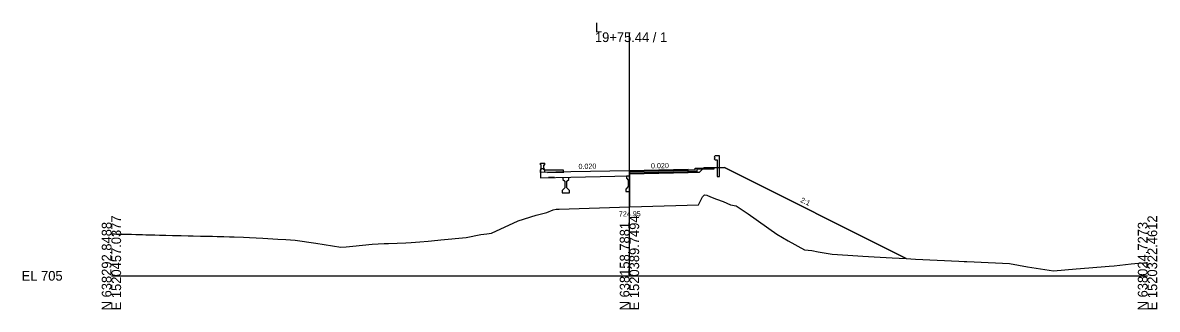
# Model space of a CAD drawing. Extents: x -26 to 3903, y -10 to 9531.
# Drawn here: x 2274.3 to 2602.8, y -9.7 to 73.3 of the extents above; entities that cross this region are included whole.
import ezdxf

# ---------------------------------------------------------------- set-up
doc = ezdxf.new("R2010")
doc.units = 0
for name, color, linetype in [('Exist Cross Section Cell', 7, 'Continuous'), ('Exist XS Center Line Elevation Label', 7, 'Continuous'), ('Exist XS Ground Line', 7, 'Continuous'), ('Old_Level_63', 7, 'Continuous'), ('Prop CMT Guardrail Graphics', 7, 'Continuous'), ('Prop CMT Pvmt Course 1', 7, 'Continuous'), ('Prop CMT Pvmt Course 3', 7, 'Continuous'), ('Prop CMT Pvmt Surface', 7, 'Continuous'), ('Prop CMT Slope Grass', 7, 'Continuous'), ('Prop CMT Subgrade Earthwork', 7, 'Continuous'), ('Prop XS Conc Monolithic Island', 7, 'Continuous'), ('Prop XS Earthwork Shape', 7, 'Continuous'), ('Prop XS Finish Grade', 7, 'Continuous'), ('Prop XS Finish Grade Concrete', 7, 'Continuous'), ('Prop XS SE Text', 7, 'Continuous'), ('Prop XS Side Slope Text', 7, 'Continuous')]:
    doc.layers.add(name, color=color, linetype=linetype)

msp = doc.modelspace()

# ---------------------------------------------------------------- linework, layer by layer
at = {"layer": 'Exist Cross Section Cell'}
for p, q in [((2450, 0), (2450, 70.48)), ((2300, 0), (2450, 0)), ((2450, 0), (2600, 0))]:
    msp.add_line(p, q, dxfattribs=at)
at = {"layer": 'Exist XS Ground Line'}
msp.add_lwpolyline([(2300, 12.12), (2300.89, 12.11), (2301.45, 12.1), (2303.1, 12.08), (2305.08, 12.06), (2305.8, 12.03), (2307.02, 11.98), (2308.33, 11.95), (2309.01, 11.93), (2309.93, 11.91), (2312.01, 11.85), (2312.55, 11.84), (2313.92, 11.8), (2314.59, 11.79), (2315.77, 11.76), (2317.64, 11.71), (2318.14, 11.7), (2320.19, 11.65), (2322.25, 11.6), (2323.23, 11.58), (2323.71, 11.57), (2325.79, 11.52), (2326.94, 11.49), (2328.82, 11.45), (2329.27, 11.44), (2330.64, 11.4), (2331.4, 11.39), (2332.52, 11.36), (2334.16, 11.32), (2334.85, 11.3), (2335.54, 11.28), (2338.23, 11.2), (2340.02, 11.1), (2343.85, 10.89), (2348.14, 10.63), (2350.47, 10.49), (2353.17, 10.33), (2359.2, 9.41), (2366.38, 8.29), (2368, 8.41), (2369.94, 8.6), (2375.5, 9.18), (2379.01, 9.31), (2379.62, 9.34), (2380.26, 9.4), (2385.25, 9.53), (2386.75, 9.67), (2389.28, 9.85), (2391.7, 10.01), (2394.48, 10.32), (2395.39, 10.42), (2402.69, 11.13), (2406.92, 11.94), (2408.71, 12.12), (2410.04, 12.37), (2417.77, 15.9), (2422.95, 17.52), (2426.12, 18.33), (2427.92, 19.15), (2428.76, 19.28), (2429.65, 19.31), (2450, 19.94), (2453.47, 20.05), (2469.97, 20.6), (2471.15, 22.85), (2471.71, 23.49), (2472.44, 23.37), (2473.44, 22.88), (2475.18, 22.15), (2477.17, 21.54), (2479.25, 20.57), (2480.86, 20.25), (2484.37, 17.97), (2492.63, 12.04), (2496, 10.14), (2500.71, 7.49), (2502.76, 7.3), (2504.6, 6.95), (2508.72, 6.27), (2513.21, 5.94), (2517.56, 5.67), (2520.9, 5.45), (2526.02, 5.17), (2530.1, 5.05), (2532.8, 4.87), (2545.33, 4.26), (2546.9, 4.17), (2547.68, 4.12), (2549.77, 4.04), (2560.06, 3.56), (2565.27, 2.59), (2572.75, 1.44), (2579.34, 2.07), (2583.04, 2.34), (2588.92, 2.8), (2590.36, 2.91), (2595.3, 3.47), (2597.4, 3.7), (2598.98, 3.77), (2600, 3.8)], dxfattribs=at)
at = {"layer": 'Old_Level_63'}
for p, q in [((2467, 30.16), (2467, 30.74)), ((2469.5, 30.21), (2467, 30.16)), ((2469.5, 31.2), (2469.5, 30.21))]:
    msp.add_line(p, q, dxfattribs=at)
for points in [[(2426.29, 29.93), (2431, 30.02)], [(2467, 30.16), (2467, 30.74)], [(2469.5, 30.89), (2474.5, 30.98)], [(2474.5, 30.98), (2474.5, 31.3)], [(2428.25, 28.47), (2427.42, 28.45), (2426.58, 28.43)]]:
    msp.add_lwpolyline(points, dxfattribs=at)
at = {"layer": 'Prop CMT Guardrail Graphics'}
for points in [[(2476.11, 34.76), (2474.77, 34.76), (2474.5, 34.46)], [(2474.5, 34.46), (2474.77, 34.17)], [(2474.77, 34.17), (2474.5, 33.88)], [(2474.5, 33.88), (2474.77, 33.59), (2475.44, 33.59)], [(2475.44, 33.59), (2475.44, 28.76)], [(2476.11, 28.76), (2476.11, 34.76)], [(2475.44, 28.76), (2476.11, 28.76)]]:
    msp.add_lwpolyline(points, dxfattribs=at)
at = {"layer": 'Prop CMT Pvmt Course 1'}
msp.add_lwpolyline([(2467, 30.49), (2450, 30.15)], dxfattribs=at)
at = {"layer": 'Prop CMT Pvmt Course 3'}
msp.add_lwpolyline([(2450, 29.82), (2467, 30.16)], dxfattribs=at)
at = {"layer": 'Prop CMT Pvmt Surface'}
msp.add_line((2467, 30.74), (2450, 30.4), dxfattribs=at)
at = {"layer": 'Prop CMT Slope Grass'}
for p, q in [((2450, 30.4), (2450, 19.94)), ((2474.5, 31.3), (2477.5, 31.36)), ((2477.5, 31.36), (2530.13, 5.05))]:
    msp.add_line(p, q, dxfattribs=at)
at = {"layer": 'Prop CMT Subgrade Earthwork'}
for points in [[(2450, 29.57), (2467, 29.91)], [(2467, 29.91), (2470.25, 29.97), (2471.51, 31.24)]]:
    msp.add_lwpolyline(points, dxfattribs=at)
at = {"layer": 'Prop XS Conc Monolithic Island'}
for p, q in [((2424.22, 32.14), (2424.22, 32.64)), ((2424.22, 32.64), (2425.47, 32.64)), ((2424.47, 32.14), (2424.22, 32.14)), ((2424.22, 29.89), (2424.22, 30.64)), ((2424.22, 30.64), (2424.47, 30.64)), ((2424.47, 30.64), (2424.47, 32.14)), ((2425.22, 30.64), (2425.22, 32.14)), ((2425.22, 32.14), (2425.47, 32.14)), ((2425.47, 30.64), (2425.22, 30.64)), ((2425.47, 32.14), (2425.47, 32.64)), ((2425.47, 29.89), (2425.47, 30.64))]:
    msp.add_line(p, q, dxfattribs=at)
for points in [[(2450, 30.4), (2433, 30.06), (2424.22, 29.89)], [(2424.22, 29.89), (2424.25, 28.39)], [(2424.25, 28.39), (2433, 28.56), (2450, 28.9)], [(2430.74, 28.52), (2430.74, 27.87)], [(2430.74, 27.87), (2431.24, 27.37)], [(2431.24, 27.37), (2431.24, 25.45)], [(2431.91, 27.37), (2432.41, 27.87)], [(2431.91, 25.45), (2431.91, 27.37)], [(2432.41, 27.87), (2432.41, 28.55)], [(2450, 28.9), (2449.17, 28.88)], [(2449.17, 28.88), (2449.17, 28.23)], [(2449.17, 28.23), (2449.67, 27.73)], [(2449.67, 27.73), (2449.67, 25.82)], [(2431.24, 25.45), (2430.49, 24.7)], [(2430.49, 24.7), (2430.49, 24.03)], [(2430.49, 24.03), (2431.58, 24.03), (2432.66, 24.03)], [(2432.66, 24.7), (2431.91, 25.45)], [(2432.66, 24.03), (2432.66, 24.7)], [(2449.67, 25.82), (2448.92, 25.07)], [(2448.92, 25.07), (2448.92, 24.4)], [(2448.92, 24.4), (2450, 24.4)]]:
    msp.add_lwpolyline(points, dxfattribs=at)
at = {"layer": 'Prop XS Earthwork Shape'}
for points in [[(2520.9, 5.45), (2526.02, 5.17), (2530.13, 5.05), (2477.5, 31.36), (2474.5, 31.3), (2471.51, 31.24), (2470.25, 29.97), (2467, 29.91), (2450, 29.57), (2450, 19.94), (2453.47, 20.05), (2469.97, 20.6), (2471.15, 22.85), (2471.71, 23.49), (2472.44, 23.37), (2473.44, 22.88), (2475.18, 22.15), (2477.17, 21.54), (2479.25, 20.57), (2480.86, 20.25), (2484.37, 17.97), (2492.63, 12.04), (2496, 10.14), (2500.71, 7.49), (2502.76, 7.3), (2504.6, 6.95), (2508.72, 6.27), (2513.21, 5.94), (2517.56, 5.67)], [(2472.44, 23.37), (2473.44, 22.88), (2475.18, 22.15), (2477.17, 21.54), (2479.25, 20.57), (2480.86, 20.25), (2484.37, 17.97), (2492.63, 12.04), (2496, 10.14), (2500.71, 7.49), (2502.76, 7.3), (2504.6, 6.95), (2508.72, 6.27), (2513.21, 5.94), (2517.56, 5.67), (2520.9, 5.45), (2526.02, 5.17), (2530.13, 5.05), (2477.5, 31.36), (2474.5, 31.3), (2471.51, 31.24), (2470.25, 29.97), (2467, 29.91), (2450, 29.57), (2450, 19.94), (2453.47, 20.05), (2469.97, 20.6), (2471.15, 22.85), (2471.71, 23.49)]]:
    msp.add_lwpolyline(points, close=True, dxfattribs=at)
at = {"layer": 'Prop XS Finish Grade'}
msp.add_line((2430.93, 30.02), (2430.93, 30.58), dxfattribs=at)
msp.add_lwpolyline([(2430.93, 30.02), (2430.93, 30.58), (2425.43, 30.63), (2425.43, 30.97), (2424.22, 30.97), (2424.22, 29.89)], dxfattribs=at)
at = {"layer": 'Prop XS Finish Grade Concrete'}
for points in [[(2467, 30.74), (2469, 30.7), (2469, 31.2), (2469.5, 31.2)], [(2469.5, 31.2), (2474.5, 31.3)]]:
    msp.add_lwpolyline(points, dxfattribs=at)

# ---------------------------------------------------------------- texts
at = {"layer": 'Exist Cross Section Cell'}
for s, p in [('L', (2440, 70.48)), ('19+75.44 / 1', (2440, 67.68)), ('EL 705', (2274, -1.4))]:
    msp.add_text(s, height=2.8, dxfattribs=at).set_placement(p)
for s, p in [('E 1520457.0377', (2302.8, -10)), ('E 1520389.7494', (2452.8, -10)), ('E 1520322.4612', (2602.8, -10)), ('N 638292.8488', (2300, -10)), ('N 638158.7881', (2450, -10)), ('N 638024.7273', (2600, -10))]:
    msp.add_text(s, height=2.8, rotation=90, dxfattribs=at).set_placement(p)
at = {"layer": 'Exist XS Center Line Elevation Label'}
msp.add_text('724.95', height=1.5, rotation=0.8401, dxfattribs=at).set_placement((2446.95, 17.16))
at = {"layer": 'Prop XS SE Text'}
for p in [(2435.26, 30.91), (2456.24, 31.09)]:
    msp.add_text('0.020', height=1.5, rotation=1.1458, dxfattribs=at).set_placement(p)
at = {"layer": 'Prop XS Side Slope Text'}
msp.add_text('2:1', height=1.5, rotation=334.8977, dxfattribs=at).set_placement((2499.33, 21.43))

doc.saveas('drawing.dxf')
